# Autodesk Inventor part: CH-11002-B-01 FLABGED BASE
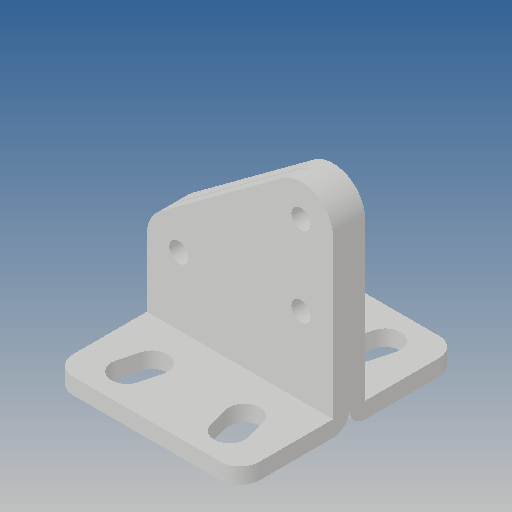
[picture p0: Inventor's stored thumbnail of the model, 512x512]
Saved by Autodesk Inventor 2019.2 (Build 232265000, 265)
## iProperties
Created: 2012-09
Part Number: CH-11002-B-01 FLABGED BASE
Material: Ogólny
Document SubType Name: Modeling
Designer: CADENGINEERING4
Density: 1 g/cm^3
Appearance: Domyślna
Author: CADENGINEERING4
Revision Number: ÈÎºÎ
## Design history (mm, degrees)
feature "ÇÐ³ý-À­Éì1"
feature "¾µÏò1"
node "Bryła1"
node "Bryła2"
